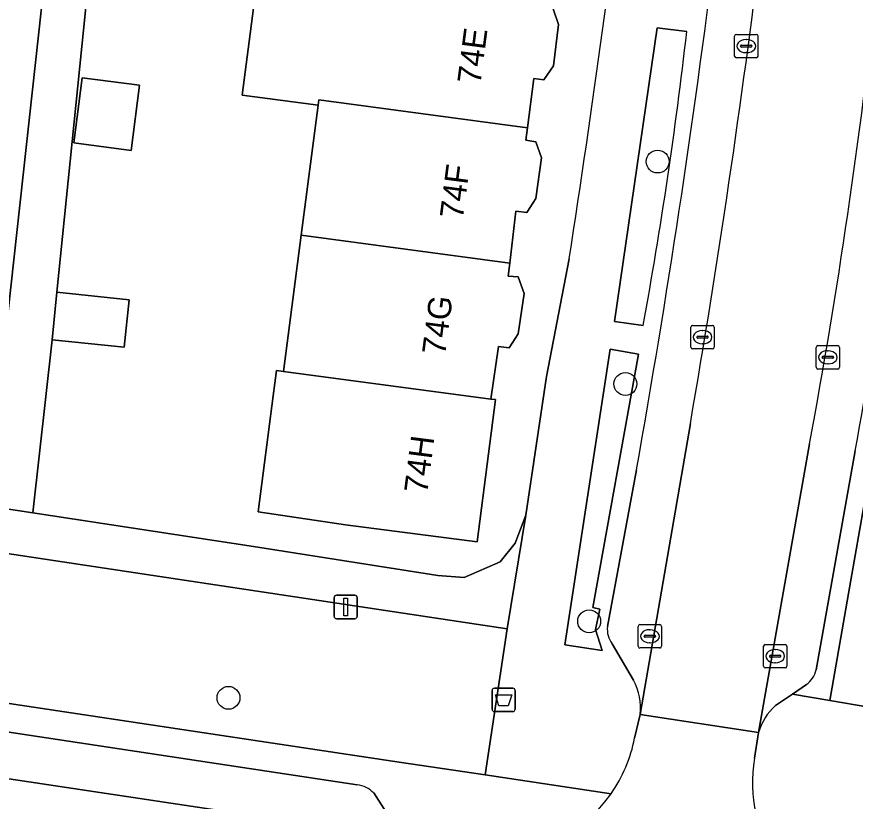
# Model space of a CAD drawing. Extents: x 163008 to 163854, y 382777 to 383982.
# Drawn here: x 163335.95 to 163371.81, y 383251.53 to 383285.09 of the extents above; entities that cross this region are included whole.
import ezdxf

# ---------------------------------------------------------------- set-up
doc = ezdxf.new("R2010")
doc.units = 0
for name, color, linetype in [('IMGEO_Afvalbak', 7, 'Continuous'), ('IMGEO_Boom', 7, 'Continuous'), ('IMGEO_Erf', 7, 'Continuous'), ('IMGEO_Groenvoorziening', 7, 'Continuous'), ('IMGEO_Haag', 7, 'Continuous'), ('IMGEO_Kolk', 7, 'Continuous'), ('IMGEO_Lichtmast', 7, 'Continuous'), ('IMGEO_Muur', 7, 'Continuous'), ('IMGEO_Pand', 7, 'Continuous'), ('IMGEO_Pand_nummerreeks', 7, 'Continuous'), ('IMGEO_Parkeervlak_open', 7, 'Continuous'), ('IMGEO_Rijbaan_lokaal_gesloten', 7, 'Continuous'), ('IMGEO_Voetpad_open', 7, 'Continuous')]:
    doc.layers.add(name, color=color, linetype=linetype)

msp = doc.modelspace()

# ---------------------------------------------------------------- linework, layer by layer
at = {"layer": 'IMGEO_Afvalbak'}
for p, q in [((163356.274, 383255.466), (163356.274, 383256.266)), ((163356.274, 383256.266), (163356.274, 383255.466)), ((163356.374, 383256.366), (163357.164, 383256.366)), ((163357.164, 383256.366), (163356.374, 383256.366)), ((163357.264, 383256.266), (163357.264, 383255.466)), ((163357.264, 383255.466), (163357.264, 383256.266)), ((163357.164, 383255.366), (163356.374, 383255.366)), ((163356.374, 383255.366), (163357.164, 383255.366))]:
    msp.add_line(p, q, dxfattribs=at)
msp.add_lwpolyline([(163356.417, 383256.08), (163357.121, 383256.08), (163356.972, 383255.61), (163356.566, 383255.61), (163356.417, 383256.08)], dxfattribs=at)
for centre, start, end in [((163356.374, 383256.266), 90, 180), ((163356.374, 383256.266), 90, 180), ((163357.164, 383256.266), 0, 90), ((163357.164, 383256.266), 360, 90), ((163356.374, 383255.466), 180, 270), ((163356.374, 383255.466), 180, 270), ((163357.164, 383255.466), 270, 0), ((163357.164, 383255.466), 270, 0)]:
    msp.add_arc(centre, 0.1, start, end, dxfattribs=at)
at = {"layer": 'IMGEO_Boom'}
for centre in [(163363.356, 383278.896), (163361.98, 383269.382), (163360.43, 383259.229), (163345.005, 383255.955)]:
    msp.add_circle(centre, 0.489, dxfattribs=at)
at = {"layer": 'IMGEO_Erf'}
for points in [[(163253.685, 383276.401), (163334.658, 383264.168), (163337.516, 383290.164), (163336.092, 383290.332), (163336.046, 383289.91), (163335.73, 383287.002), (163332.932, 383287.306), (163333.066, 383288.538), (163333.297, 383290.663), (163333.239, 383290.669), (163327.49, 383291.348), (163315.763, 383292.563), (163315.439, 383289.298), (163312.515, 383289.589), (163310.225, 383289.816), (163310.549, 383293.081), (163304.2, 383293.711), (163303.785, 383290.139), (163300.841, 383290.481), (163298.433, 383290.761), (163298.858, 383294.419)], [(163339.549, 383291.816), (163337.671, 383273.302), (163340.757, 383272.983), (163340.547, 383270.953), (163337.461, 383271.272), (163336.64, 383263.869), (163346.081, 383262.43), (163353.958, 383261.185), (163355.085, 383261.097), (163356.63, 383261.773), (163357.262, 383262.567), (163357.715, 383263.771), (163358.603, 383269.699), (163359.577, 383274.731)], [(163358.883, 383285.431), (163359.112, 383284.754), (163358.907, 383282.996), (163358.49, 383282.39), (163358.058, 383282.451), (163357.787, 383280.342), (163357.718, 383279.806), (163358.145, 383279.746), (163358.388, 383279.059), (163358.146, 383277.308), (163357.757, 383276.713), (163357.296, 383276.767), (163357.036, 383274.547), (163356.971, 383273.988), (163357.387, 383273.959), (163357.643, 383273.257), (163357.398, 383271.532), (163357.004, 383270.924), (163356.547, 383270.983), (163356.231, 383268.736), (163356.43, 383268.71), (163355.636, 383262.63), (163350.003, 383263.358), (163346.272, 383263.908), (163346.912, 383268.867), (163347.053, 383269.955), (163347.351, 383269.915), (163348.11, 383275.743), (163348.836, 383281.308), (163345.585, 383281.732), (163346.33, 383287.44)]]:
    msp.add_lwpolyline(points, dxfattribs=at)
msp.add_lwpolyline([(163340.842, 383279.37), (163338.388, 383279.69), (163338.751, 383282.478), (163341.205, 383282.159)], close=True, dxfattribs=at)
msp.add_arc((162826.004, 383357.474), 539.95, 351.18512, 353.28089, dxfattribs=at)
at = {"layer": 'IMGEO_Groenvoorziening'}
msp.add_lwpolyline([(163364.602, 383284.454), (163363.341, 383284.617), (163361.508, 383272.052), (163362.737, 383271.884)], dxfattribs=at)
for points in [[(163360.703, 383258.884), (163360.882, 383259.748), (163360.59, 383259.824), (163362.539, 383270.653), (163361.322, 383270.868), (163359.389, 383258.216), (163360.979, 383257.98)], [(163370.721, 383255.841), (163372.383, 383255.552), (163374.272, 383270.344), (163373.287, 383270.491), (163371.617, 383260.987)], [(163356.923, 383258.905), (163330.615, 383262.877), (163329.641, 383256.604), (163352.308, 383253.207), (163355.98, 383252.657)]]:
    msp.add_lwpolyline(points, close=True, dxfattribs=at)
msp.add_arc((163180.009, 383305.419), 185.78, 349.6007, 353.52058, dxfattribs=at)
at = {"layer": 'IMGEO_Haag'}
msp.add_lwpolyline([(163364.602, 383284.454), (163363.341, 383284.617), (163361.508, 383272.052), (163362.737, 383271.884)], dxfattribs=at)
for points in [[(163360.703, 383258.884), (163360.882, 383259.748), (163360.59, 383259.824), (163362.539, 383270.653), (163361.322, 383270.868), (163359.389, 383258.216), (163360.979, 383257.98)], [(163370.721, 383255.841), (163372.383, 383255.552), (163374.272, 383270.344), (163373.287, 383270.491), (163371.617, 383260.987)]]:
    msp.add_lwpolyline(points, close=True, dxfattribs=at)
msp.add_arc((163180.009, 383305.419), 185.78, 349.6007, 353.52058, dxfattribs=at)
at = {"layer": 'IMGEO_Kolk'}
for p, q in [((163366.648, 383283.409), (163366.648, 383284.261)), ((163366.723, 383284.335), (163367.575, 383284.335)), ((163367.649, 383284.261), (163367.649, 383283.409)), ((163366.907, 383283.829), (163366.907, 383283.841)), ((163367.345, 383283.792), (163366.947, 383283.792)), ((163366.95, 383283.878), (163367.348, 383283.878)), ((163367.136, 383284.115), (163367.161, 383284.115)), ((163367.391, 383283.841), (163367.391, 383283.829)), ((163367.159, 383283.555), (163367.134, 383283.555)), ((163367.575, 383283.335), (163366.723, 383283.335)), ((163364.777, 383270.957), (163364.777, 383271.809)), ((163364.852, 383271.883), (163365.704, 383271.883)), ((163365.265, 383271.663), (163365.29, 383271.663)), ((163365.778, 383271.809), (163365.778, 383270.957)), ((163365.036, 383271.377), (163365.036, 383271.389)), ((163365.474, 383271.34), (163365.076, 383271.34)), ((163365.079, 383271.426), (163365.477, 383271.426)), ((163365.52, 383271.389), (163365.52, 383271.377)), ((163365.704, 383270.883), (163364.852, 383270.883)), ((163365.288, 383271.103), (163365.263, 383271.103)), ((163370.136, 383270.095), (163370.136, 383270.947)), ((163370.211, 383271.021), (163371.063, 383271.021)), ((163371.137, 383270.947), (163371.137, 383270.095)), ((163370.395, 383270.515), (163370.395, 383270.527)), ((163370.438, 383270.564), (163370.836, 383270.564)), ((163370.624, 383270.801), (163370.649, 383270.801)), ((163370.879, 383270.527), (163370.879, 383270.515)), ((163370.833, 383270.478), (163370.435, 383270.478)), ((163370.647, 383270.241), (163370.622, 383270.241)), ((163371.063, 383270.021), (163370.211, 383270.021)), ((163362.603, 383259.086), (163363.455, 383259.086)), ((163362.528, 383258.16), (163362.528, 383259.012)), ((163363.016, 383258.866), (163363.041, 383258.866)), ((163363.529, 383259.012), (163363.529, 383258.16)), ((163362.787, 383258.58), (163362.787, 383258.592)), ((163363.225, 383258.543), (163362.827, 383258.543)), ((163362.83, 383258.629), (163363.228, 383258.629)), ((163363.039, 383258.306), (163363.014, 383258.306)), ((163363.271, 383258.592), (163363.271, 383258.58)), ((163363.455, 383258.086), (163362.603, 383258.086)), ((163367.884, 383257.31), (163367.884, 383258.162)), ((163367.959, 383258.236), (163368.811, 383258.236)), ((163368.372, 383258.016), (163368.397, 383258.016)), ((163368.885, 383258.162), (163368.885, 383257.31)), ((163368.143, 383257.73), (163368.143, 383257.742)), ((163368.581, 383257.693), (163368.183, 383257.693)), ((163368.186, 383257.779), (163368.584, 383257.779)), ((163368.627, 383257.742), (163368.627, 383257.73)), ((163368.811, 383257.236), (163367.959, 383257.236)), ((163368.395, 383257.456), (163368.37, 383257.456))]:
    msp.add_line(p, q, dxfattribs=at)
for points in [[(163366.648, 383283.409), (163366.648, 383284.261)], [(163366.723, 383284.335), (163367.575, 383284.335)], [(163367.649, 383284.261), (163367.649, 383283.409)], [(163367.575, 383283.335), (163366.723, 383283.335)], [(163364.777, 383270.957), (163364.777, 383271.809)], [(163364.852, 383271.883), (163365.704, 383271.883)], [(163365.778, 383271.809), (163365.778, 383270.957)], [(163365.704, 383270.883), (163364.852, 383270.883)], [(163370.136, 383270.095), (163370.136, 383270.947)], [(163370.211, 383271.021), (163371.063, 383271.021)], [(163371.137, 383270.947), (163371.137, 383270.095)], [(163371.063, 383270.021), (163370.211, 383270.021)], [(163362.603, 383259.086), (163363.455, 383259.086)], [(163362.528, 383258.16), (163362.528, 383259.012)], [(163363.529, 383259.012), (163363.529, 383258.16)], [(163363.455, 383258.086), (163362.603, 383258.086)], [(163367.884, 383257.31), (163367.884, 383258.162)], [(163367.959, 383258.236), (163368.811, 383258.236)], [(163368.885, 383258.162), (163368.885, 383257.31)], [(163368.811, 383257.236), (163367.959, 383257.236)]]:
    msp.add_lwpolyline(points, dxfattribs=at)
for centre, radius, start, end in [((163366.725, 383284.259), 0.0765, 91.552, 178.448), ((163366.725, 383284.259), 0.0765, 91.552, 178.448), ((163367.573, 383284.259), 0.0765, 1.552, 88.448), ((163367.573, 383284.259), 0.0765, 1.552, 88.448), ((163366.947, 383283.838), 0.0403, 85.8775, 175.7526), ((163366.944, 383283.828), 0.0366, 178.938, 274.7102), ((163367.348, 383283.835), 0.043, 264.8664, 352.4533), ((163367.352, 383283.84), 0.0386, 1.7309, 96.639), ((163366.725, 383283.411), 0.0765, 181.552, 268.448), ((163366.725, 383283.411), 0.0765, 181.552, 268.448), ((163367.573, 383283.411), 0.0765, 271.552, 358.448), ((163367.573, 383283.411), 0.0765, 271.552, 358.448), ((163364.854, 383271.807), 0.0765, 91.552, 178.448), ((163364.854, 383271.807), 0.0765, 91.552, 178.448), ((163365.702, 383271.807), 0.0765, 1.552, 88.448), ((163365.702, 383271.807), 0.0765, 1.552, 88.448), ((163365.076, 383271.386), 0.0403, 85.8775, 175.7526), ((163365.073, 383271.376), 0.0366, 178.938, 274.7102), ((163365.477, 383271.383), 0.043, 264.8664, 352.4533), ((163365.481, 383271.388), 0.0386, 1.7309, 96.639), ((163364.854, 383270.959), 0.0765, 181.552, 268.448), ((163364.854, 383270.959), 0.0765, 181.552, 268.448), ((163365.702, 383270.959), 0.0765, 271.552, 358.448), ((163365.702, 383270.959), 0.0765, 271.552, 358.448), ((163370.213, 383270.945), 0.0765, 91.552, 178.448), ((163370.213, 383270.945), 0.0765, 91.552, 178.448), ((163371.061, 383270.945), 0.0765, 1.552, 88.448), ((163371.061, 383270.945), 0.0765, 1.552, 88.448), ((163370.435, 383270.524), 0.0403, 85.8775, 175.7526), ((163370.432, 383270.514), 0.0366, 178.938, 274.7102), ((163370.836, 383270.521), 0.043, 264.8664, 352.4533), ((163370.84, 383270.526), 0.0386, 1.7309, 96.639), ((163370.213, 383270.097), 0.0765, 181.552, 268.448), ((163370.213, 383270.097), 0.0765, 181.552, 268.448), ((163371.061, 383270.097), 0.0765, 271.552, 358.448), ((163371.061, 383270.097), 0.0765, 271.552, 358.448), ((163362.605, 383259.01), 0.0765, 91.552, 178.448), ((163362.605, 383259.01), 0.0765, 91.552, 178.448), ((163363.453, 383259.01), 0.0765, 1.552, 88.448), ((163363.453, 383259.01), 0.0765, 1.552, 88.448), ((163362.827, 383258.589), 0.0403, 85.8775, 175.7526), ((163362.824, 383258.579), 0.0366, 178.938, 274.7102), ((163363.228, 383258.586), 0.043, 264.8664, 352.4533), ((163363.232, 383258.591), 0.0386, 1.7309, 96.639), ((163362.605, 383258.162), 0.0765, 181.552, 268.448), ((163362.605, 383258.162), 0.0765, 181.552, 268.448), ((163363.453, 383258.162), 0.0765, 271.552, 358.448), ((163363.453, 383258.162), 0.0765, 271.552, 358.448), ((163367.961, 383258.16), 0.0765, 91.552, 178.448), ((163367.961, 383258.16), 0.0765, 91.552, 178.448), ((163368.809, 383258.16), 0.0765, 1.552, 88.448), ((163368.809, 383258.16), 0.0765, 1.552, 88.448), ((163368.183, 383257.739), 0.0403, 85.8775, 175.7526), ((163368.18, 383257.729), 0.0366, 178.938, 274.7102), ((163368.584, 383257.736), 0.043, 264.8664, 352.4533), ((163368.588, 383257.741), 0.0386, 1.7309, 96.639), ((163367.961, 383257.312), 0.0765, 181.552, 268.448), ((163367.961, 383257.312), 0.0765, 181.552, 268.448), ((163368.809, 383257.312), 0.0765, 271.552, 358.448), ((163368.809, 383257.312), 0.0765, 271.552, 358.448)]:
    msp.add_arc(centre, radius, start, end, dxfattribs=at)
for centre, major_axis, ratio, start_param, end_param in [((163367.135, 383283.835), (-0.387, 0.002), 0.722429, 4.712389, 7.853982), ((163367.16, 383283.835), (-0.39, 0.002), 0.717154, 1.570796, 4.712389), ((163365.264, 383271.383), (-0.387, 0.002), 0.722429, 4.712389, 7.853982), ((163365.289, 383271.383), (-0.39, 0.002), 0.717154, 1.570796, 4.712389), ((163370.623, 383270.521), (-0.387, 0.002), 0.722429, 4.712389, 7.853982), ((163370.648, 383270.521), (-0.39, 0.002), 0.717154, 1.570796, 4.712389), ((163363.015, 383258.586), (-0.387, 0.002), 0.722429, 4.712389, 7.853982), ((163363.04, 383258.586), (-0.39, 0.002), 0.717154, 1.570796, 4.712389), ((163368.371, 383257.736), (-0.387, 0.002), 0.722429, 4.712389, 7.853982), ((163368.396, 383257.736), (-0.39, 0.002), 0.717154, 1.570796, 4.712389)]:
    msp.add_ellipse(centre, major_axis=major_axis, ratio=ratio, start_param=start_param, end_param=end_param, dxfattribs=at)
at = {"layer": 'IMGEO_Lichtmast'}
for p, q in [((163349.521, 383259.44), (163349.521, 383260.24)), ((163349.521, 383260.24), (163349.521, 383259.44)), ((163349.621, 383260.34), (163350.411, 383260.34)), ((163350.411, 383260.34), (163349.621, 383260.34)), ((163350.511, 383260.24), (163350.511, 383259.44)), ((163350.511, 383259.44), (163350.511, 383260.24)), ((163350.411, 383259.34), (163349.621, 383259.34)), ((163349.621, 383259.34), (163350.411, 383259.34))]:
    msp.add_line(p, q, dxfattribs=at)
msp.add_lwpolyline([(163349.941, 383260.215), (163350.091, 383260.215), (163350.091, 383259.465), (163349.941, 383259.465), (163349.941, 383260.215)], dxfattribs=at)
for centre, start, end in [((163349.621, 383260.24), 90, 180), ((163349.621, 383260.24), 90, 180), ((163350.411, 383260.24), 0, 90), ((163350.411, 383260.24), 360, 90), ((163349.621, 383259.44), 180, 270), ((163349.621, 383259.44), 180, 270), ((163350.411, 383259.44), 270, 0), ((163350.411, 383259.44), 270, 0)]:
    msp.add_arc(centre, 0.1, start, end, dxfattribs=at)
at = {"layer": 'IMGEO_Muur'}
msp.add_lwpolyline([(163346.081, 383262.43), (163336.64, 383263.869)], dxfattribs=at)
at = {"layer": 'IMGEO_Pand'}
for points in [[(163358.883, 383285.431), (163358.459, 383285.483), (163358.529, 383285.904), (163358.812, 383285.864), (163358.846, 383286.128), (163349.327, 383287.388), (163349.288, 383287.091), (163349.283, 383287.055), (163346.33, 383287.44), (163345.585, 383281.732), (163348.836, 383281.308), (163348.866, 383281.541), (163357.787, 383280.342), (163358.058, 383282.451), (163358.49, 383282.39), (163358.907, 383282.996), (163359.112, 383284.754)], [(163338.388, 383279.69), (163340.842, 383279.37), (163341.205, 383282.159), (163338.751, 383282.478)], [(163358.388, 383279.059), (163358.145, 383279.746), (163357.718, 383279.806), (163357.787, 383280.342), (163348.866, 383281.541), (163348.836, 383281.308), (163348.11, 383275.743), (163357.036, 383274.547), (163357.296, 383276.767), (163357.757, 383276.713), (163358.146, 383277.308)], [(163357.643, 383273.257), (163357.387, 383273.959), (163356.971, 383273.988), (163357.036, 383274.547), (163348.11, 383275.743), (163347.351, 383269.915), (163356.231, 383268.736), (163356.547, 383270.983), (163357.004, 383270.924), (163357.398, 383271.532)], [(163337.671, 383273.302), (163337.461, 383271.272), (163340.547, 383270.953), (163340.757, 383272.983)], [(163356.43, 383268.71), (163356.231, 383268.736), (163347.351, 383269.915), (163347.053, 383269.955), (163346.912, 383268.867), (163346.272, 383263.908), (163350.003, 383263.358), (163355.636, 383262.63)]]:
    msp.add_lwpolyline(points, close=True, dxfattribs=at)
at = {"layer": 'IMGEO_Parkeervlak_open'}
for points in [[(163362.611, 383255.237), (163364.759, 383267.696)], [(163369.852, 383266.813), (163367.665, 383254.464)], [(163370.135, 383257.156), (163371.807, 383266.52)], [(163362.452, 383265.714), (163361.212, 383259.009)], [(163350.515, 383252.239), (163291.697, 383261.137)], [(163288.229, 383259.608), (163352.608, 383249.943), (163352.169, 383250.391), (163351.214, 383251.883)], [(163361.407, 383258.262), (163362.328, 383256.704)], [(163368.394, 383255.623), (163369.125, 383256.115), (163369.724, 383256.518)]]:
    msp.add_lwpolyline(points, dxfattribs=at)
for centre, radius, start, end in [((162942.185, 383340.698), 426.904, 349.88374, 355.92186), ((162946.37, 383340.015), 424.593, 350.19333, 355.81501), ((163115.319, 383314.225), 258.911, 349.44837, 353.86233), ((163029.838, 383327.884), 347.431, 349.82699, 352.6073), ((163362.277, 383258.888), 1.072, 173.5225, 215.738), ((163369.022, 383257.421), 1.144, 307.8373, 346.5834), ((163360.043, 383255.502), 2.582, 354.1026, 27.7351), ((163370.096, 383253.744), 2.535, 132.1642, 163.4968), ((163350.361, 383251.073), 1.176, 43.5353, 82.4853)]:
    msp.add_arc(centre, radius, start, end, dxfattribs=at)
at = {"layer": 'IMGEO_Rijbaan_lokaal_gesloten'}
for points in [[(163364.759, 383267.696), (163362.611, 383255.237), (163367.665, 383254.464), (163369.852, 383266.813)], [(163367.494, 383253.369), (163367.665, 383254.464), (163362.611, 383255.237), (163362.374, 383254.232)]]:
    msp.add_lwpolyline(points, dxfattribs=at)
msp.add_lwpolyline([(163285.184, 383258.317), (163352.91, 383248.164), (163353.412, 383249.506), (163352.608, 383249.943), (163288.229, 383259.608), (163286.363, 383259.893), (163285.467, 383260.115)], close=True, dxfattribs=at)
for centre, radius, start, end in [((162946.37, 383340.015), 424.593, 350.19333, 355.81501), ((163115.319, 383314.225), 258.911, 349.44837, 353.86233), ((163356.208, 383255.435), 6.282, 325.1873, 348.9563), ((163373.809, 383252.336), 6.399, 170.7144, 254.9061), ((163356.199, 383255.438), 6.291, 262.6685, 325.2191)]:
    msp.add_arc(centre, radius, start, end, dxfattribs=at)
at = {"layer": 'IMGEO_Voetpad_open'}
for points in [[(163369.724, 383256.518), (163369.125, 383256.115), (163370.721, 383255.841), (163371.617, 383260.987), (163373.287, 383270.491), (163374.272, 383270.344), (163372.383, 383255.552), (163374.154, 383255.273), (163378.362, 383287.459), (163378.571, 383287.42), (163379.265, 383293.4), (163379.898, 383293.303), (163383.373, 383292.769), (163387.494, 383292.151)], [(163362.737, 383271.884), (163361.508, 383272.052), (163363.341, 383284.617), (163364.602, 383284.454)], [(163361.366, 383251.849), (163355.98, 383252.657), (163352.308, 383253.207), (163329.641, 383256.604), (163330.615, 383262.877), (163356.923, 383258.905), (163357.715, 383263.771), (163357.262, 383262.567), (163356.63, 383261.773), (163355.085, 383261.097), (163353.958, 383261.185), (163346.081, 383262.43), (163336.64, 383263.869), (163334.658, 383264.168), (163253.685, 383276.401)], [(163359.577, 383274.731), (163358.603, 383269.699), (163357.715, 383263.771), (163356.923, 383258.905), (163355.98, 383252.657), (163361.366, 383251.849)], [(163371.807, 383266.52), (163370.135, 383257.156)], [(163361.212, 383259.009), (163362.452, 383265.714)], [(163291.697, 383261.137), (163350.515, 383252.239)], [(163362.328, 383256.704), (163361.407, 383258.262)], [(163414.745, 383249.151), (163398.861, 383251.572), (163397.974, 383251.687), (163397.808, 383251.712), (163393.553, 383252.351), (163387.514, 383253.257), (163383.017, 383253.931), (163379.126, 383254.52), (163374.154, 383255.273), (163372.383, 383255.552), (163370.721, 383255.841), (163369.125, 383256.115), (163368.394, 383255.623)], [(163362.374, 383254.232), (163362.611, 383255.237)], [(163367.665, 383254.464), (163367.494, 383253.369)], [(163351.214, 383251.883), (163352.169, 383250.391), (163352.608, 383249.943), (163353.412, 383249.506), (163355.396, 383249.198)]]:
    msp.add_lwpolyline(points, dxfattribs=at)
for points in [[(163339.549, 383291.816), (163333.483, 383292.463), (163333.239, 383290.669), (163333.297, 383290.663), (163333.303, 383290.721), (163336.101, 383290.416), (163336.092, 383290.332), (163337.516, 383290.164), (163334.658, 383264.168), (163336.64, 383263.869), (163337.461, 383271.272), (163337.671, 383273.302)], [(163362.539, 383270.653), (163360.59, 383259.824), (163360.882, 383259.748), (163360.703, 383258.884), (163360.979, 383257.98), (163359.389, 383258.216), (163361.322, 383270.868)]]:
    msp.add_lwpolyline(points, close=True, dxfattribs=at)
for centre, radius, start, end in [((162942.185, 383340.698), 426.904, 349.88374, 355.92186), ((162826.004, 383357.474), 539.95, 351.18512, 353.28089), ((163180.009, 383305.419), 185.78, 349.6007, 353.52058), ((163029.838, 383327.884), 347.431, 349.82699, 352.6073), ((163362.277, 383258.888), 1.072, 173.5225, 215.738), ((163369.022, 383257.421), 1.144, 307.8373, 346.5834), ((163360.043, 383255.502), 2.582, 354.1026, 27.7351), ((163370.096, 383253.744), 2.535, 132.1642, 163.4968), ((163356.208, 383255.435), 6.282, 325.1873, 348.9563), ((163373.809, 383252.336), 6.399, 170.7144, 254.9061), ((163350.361, 383251.073), 1.176, 43.5353, 82.4853), ((163356.199, 383255.438), 6.291, 262.6685, 325.2191)]:
    msp.add_arc(centre, radius, start, end, dxfattribs=at)

# ---------------------------------------------------------------- texts
at = {"layer": 'IMGEO_Pand_nummerreeks'}
for s, rotation, p in [('74E', 82.5861, (163355.777, 383282.175)), ('74F', 82.5861, (163355.027, 383276.409)), ('74G', 82.5861, (163354.269, 383270.584)), ('74H', 82.6377, (163353.502, 383264.664))]:
    msp.add_text(s, height=1, rotation=rotation, dxfattribs=at).set_placement(p)

doc.saveas('drawing.dxf')
